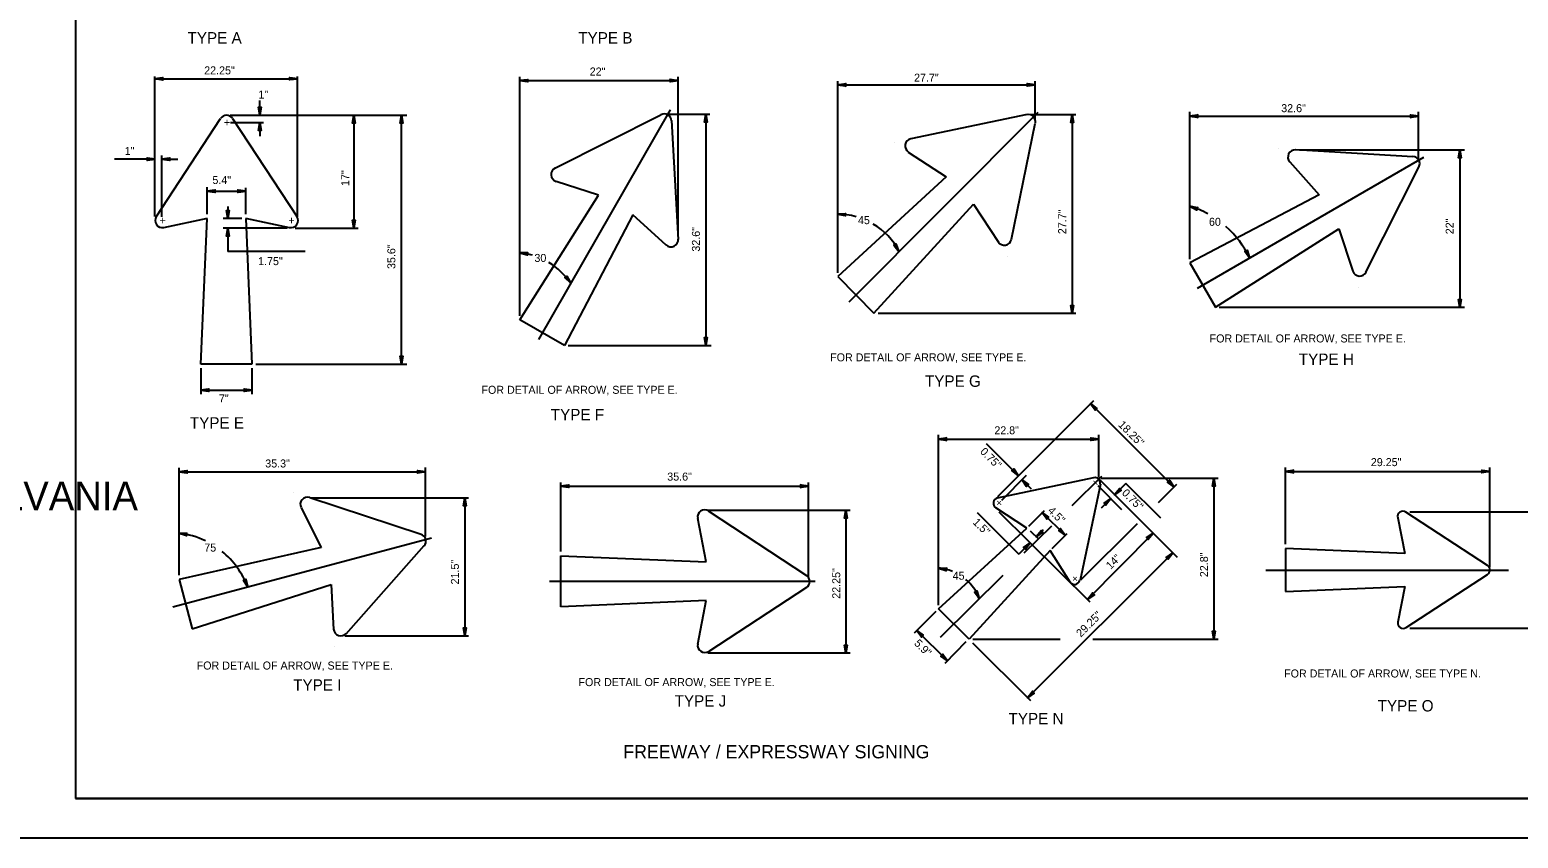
# Model space of a CAD drawing. Extents: x 638421 to 641849, y 297270 to 299646.
# Drawn here: x 640967 to 641529, y 298458 to 298763 of the extents above; entities that cross this region are included whole.
import ezdxf

# ---------------------------------------------------------------- set-up
doc = ezdxf.new("R2010")
doc.units = 0
for name, color, linetype in [('1', 7, 'Continuous'), ('2', 7, 'Continuous'), ('3', 7, 'Continuous'), ('XCS-GRID-HVGL', 7, 'Continuous')]:
    doc.layers.add(name, color=color, linetype=linetype)

# ---------------------------------------------------------------- blocks, each defined once
blk = doc.blocks.new('RARROW')
at = {"layer": '3'}
blk.add_lwpolyline([(-2.2695, 0.285), (-2.184875, 0.12075), (0, 0), (-2.2695, 0.285), (-2.38575, 0.384625), (0, 0), (-2.183125, -0.108), (-2.262875, -0.2705), (0, 0), (-2.38575, -0.379125), (-2.262875, -0.2705)], dxfattribs=at)

msp = doc.modelspace()

# ---------------------------------------------------------------- linework, layer by layer
at = {"layer": '1'}
for p, q in [((640984.31, 299036.63), (640984.31, 298472.63)), ((641770.31, 298472.63), (640984.31, 298472.63)), ((640984.31, 298472.63), (641570.31, 298472.63))]:
    msp.add_line(p, q, dxfattribs=at)
at = {"layer": '2'}
for p, q in [((641014.31, 298692.13), (641014.31, 298745)), ((641014.31, 298744.13), (641068.06, 298744.13)), ((641068.06, 298692), (641068.06, 298745)), ((641152.06, 298654.63), (641152.06, 298744.88)), ((641152.06, 298743.38), (641211.81, 298743.38)), ((641211.81, 298685.13), (641211.81, 298744.88)), ((641272.06, 298670.88), (641272.06, 298743.25)), ((641272.06, 298741.75), (641346.56, 298741.75)), ((641346.56, 298729), (641346.56, 298743.25)), ((641053.94, 298730.38), (641053.94, 298735.88)), ((641042.69, 298730.38), (641109.36, 298730.38)), ((641042.69, 298730.38), (641091.06, 298730.38)), ((641044.19, 298730.38), (641055.31, 298730.38)), ((641089.44, 298730.38), (641089.44, 298687.75)), ((641107.36, 298636.5), (641107.36, 298730.38)), ((641159.19, 298645.75), (641208.94, 298732.38)), ((641165.31, 298710.38), (641205.31, 298730.5)), ((641208.06, 298730.75), (641223.81, 298730.75)), ((641208.94, 298732.38), (641208.94, 298732.38)), ((641208.94, 298732.38), (641208.94, 298732.38)), ((641222.31, 298730.75), (641222.31, 298643.5)), ((641276.31, 298660), (641347.69, 298731.5)), ((641343.56, 298730.63), (641299.69, 298721.38)), ((641344.94, 298730.63), (641361.94, 298730.63)), ((641347.56, 298731.38), (641347.56, 298731.38)), ((641347.56, 298731.38), (641347.56, 298731.38)), ((641360.56, 298730.63), (641360.56, 298655.63)), ((641404.94, 298676), (641404.94, 298731.63)), ((641404.94, 298730), (641491.31, 298730)), ((641491.31, 298713.63), (641491.31, 298731.63)), ((641014.81, 298692), (641039.06, 298729.13)), ((641042.81, 298727.63), (641055.31, 298727.63)), ((641043.56, 298729.13), (641067.94, 298692)), ((641053.94, 298727.63), (641053.94, 298722.5)), ((641209.31, 298728.38), (641211.81, 298683.5)), ((641337.69, 298683.63), (641346.56, 298727.25)), ((641293.31, 298720.13), (641293.31, 298720.13)), ((641014.31, 298713.75), (640999.05, 298713.75)), ((641014.31, 298692.13), (641014.31, 298715.13)), ((641016.94, 298692), (641016.94, 298715.13)), ((641016.94, 298713.75), (641022.94, 298713.75)), ((641298.69, 298716.38), (641312.94, 298707.13)), ((641407.81, 298665.13), (641493.31, 298714.5)), ((641438.31, 298717.63), (641438.31, 298717.63)), ((641442.69, 298712.75), (641453.81, 298700.25)), ((641489.19, 298714.63), (641444.94, 298717.25)), ((641446.31, 298717.25), (641508.69, 298717.25)), ((641493.31, 298714.5), (641493.31, 298714.5)), ((641493.31, 298714.5), (641493.31, 298714.5)), ((641506.94, 298717.25), (641506.94, 298657.88)), ((641312.94, 298707.13), (641272.06, 298669.5)), ((641312.94, 298707.13), (641312.94, 298707.13)), ((641471.44, 298671.13), (641491.44, 298710.75)), ((641034.06, 298693), (641034.06, 298703.16)), ((641034.06, 298701.71), (641048.56, 298701.71)), ((641048.56, 298693), (641048.56, 298702.92)), ((641181.81, 298700.13), (641165.81, 298705.38)), ((641318.19, 298702), (641318.19, 298702)), ((641041.81, 298695.88), (641041.81, 298691.38)), ((641152.06, 298653.13), (641181.81, 298700.13)), ((641181.81, 298700.13), (641181.81, 298700.13)), ((641188.31, 298696.38), (641188.31, 298696.38)), ((641285.69, 298655.63), (641323.31, 298696.75)), ((641323.31, 298696.75), (641323.31, 298696.75)), ((641323.31, 298696.75), (641332.69, 298682.5)), ((641453.81, 298700.25), (641404.94, 298674.63)), ((641453.81, 298700.25), (641453.81, 298700.25)), ((641034.06, 298691.38), (641017.56, 298687.88)), ((641031.69, 298636.5), (641034.06, 298691.38)), ((641034.06, 298691.38), (641034.06, 298691.38)), ((641047.06, 298691.38), (641040.06, 298691.38)), ((641041.44, 298691.38), (641041.44, 298691.38)), ((641048.56, 298691.38), (641048.56, 298691.38)), ((641065.06, 298687.88), (641048.56, 298691.38)), ((641048.56, 298691.38), (641050.94, 298636.5)), ((641194.69, 298692.75), (641168.94, 298643.5)), ((641194.69, 298692.75), (641194.69, 298692.75)), ((641207.31, 298681.38), (641194.69, 298692.75)), ((641457.44, 298693.88), (641457.44, 298693.88)), ((641064.19, 298687.75), (641040.06, 298687.75)), ((641041.81, 298687.75), (641041.81, 298678.88)), ((641067.19, 298687.75), (641091.06, 298687.75)), ((641414.69, 298657.88), (641461.19, 298687.5)), ((641461.19, 298687.5), (641461.19, 298687.5)), ((641461.19, 298687.5), (641466.44, 298671.5)), ((641071.07, 298678.88), (641041.81, 298678.88)), ((641336.31, 298677), (641336.31, 298677)), ((641404.94, 298674.63), (641404.94, 298674.63)), ((641404.94, 298674.63), (641414.69, 298657.88)), ((641272.06, 298669.5), (641272.06, 298669.5)), ((641272.06, 298669.5), (641285.69, 298655.63)), ((641468.56, 298665.25), (641468.56, 298665.25)), ((641414.69, 298657.88), (641414.69, 298657.88)), ((641416.06, 298657.88), (641508.69, 298657.88)), ((641152.06, 298653.13), (641152.06, 298653.13)), ((641168.94, 298643.5), (641152.06, 298653.13)), ((641285.69, 298655.63), (641285.69, 298655.63)), ((641287.31, 298655.63), (641361.94, 298655.63)), ((641168.94, 298643.5), (641168.94, 298643.5)), ((641170.31, 298643.5), (641224.31, 298643.5)), ((641050.94, 298636.5), (641031.69, 298636.5)), ((641031.69, 298634.88), (641031.69, 298625.13)), ((641050.94, 298634.88), (641050.94, 298625.13)), ((641052.44, 298636.5), (641109.36, 298636.5)), ((641031.69, 298626.63), (641050.94, 298626.63)), ((641332.44, 298586.5), (641368.69, 298622.75)), ((641398.94, 298590.13), (641367.5, 298621.56)), ((641310.06, 298545.5), (641310.06, 298609.75)), ((641310.06, 298608.13), (641370.56, 298608.13)), ((641340.16, 298594.46), (641328.18, 298606.45)), ((641370.56, 298593.75), (641370.56, 298609.75)), ((641023.44, 298556.88), (641023.44, 298597.38)), ((641023.44, 298595.88), (641116.44, 298595.88)), ((641116.44, 298571.38), (641116.44, 298597.5)), ((641333.94, 298585.13), (641343.31, 298594.63)), ((641441.06, 298568.5), (641441.06, 298597.5)), ((641441.06, 298596), (641518.19, 298596)), ((641518.19, 298560), (641518.19, 298597.5)), ((641167.56, 298565.75), (641167.56, 298591.75)), ((641167.56, 298590.38), (641261.06, 298590.38)), ((641261.06, 298556.13), (641261.06, 298591.75)), ((641332.31, 298586), (641368.69, 298593.63)), ((641345.16, 298589.35), (641341.66, 298592.85)), ((641360.56, 298583.13), (641371.69, 298594.13)), ((641371.19, 298591.13), (641363.56, 298555)), ((641370.19, 298590.63), (641379.19, 298581.63)), ((641370.56, 298593.13), (641400.16, 298563.7)), ((641371.44, 298593.38), (641415.69, 298593.38)), ((641371.69, 298594.13), (641371.69, 298594.13)), ((641371.69, 298594.13), (641371.69, 298594.13)), ((641380.83, 298591.46), (641376.55, 298587.17)), ((641394, 298578.29), (641380.83, 298591.46)), ((641393.12, 298584.23), (641400.06, 298591.13)), ((641414.06, 298593.38), (641414.06, 298532.75)), ((641066.56, 298588.13), (641066.56, 298588.13)), ((641114.81, 298572.25), (641072.81, 298586)), ((641073.19, 298586), (641132.69, 298586)), ((641131.31, 298586), (641131.31, 298534)), ((641375.1, 298585.71), (641371.55, 298582.15)), ((641069.56, 298582.25), (641077.06, 298567.25)), ((641222.44, 298561.88), (641219.19, 298578.25)), ((641223.06, 298581.38), (641276.69, 298581.38)), ((641223.19, 298581.13), (641260.28, 298556.69)), ((641275.06, 298581.38), (641275.06, 298527.5)), ((641324.74, 298580.45), (641340.44, 298564.75)), ((641343.44, 298574.63), (641331.69, 298582.25)), ((641332.93, 298580.71), (641367.2, 298546.75)), ((641344.19, 298575.38), (641350.08, 298581.27)), ((641349.26, 298580.51), (641357.89, 298571.88)), ((641483.43, 298578.51), (641486.19, 298565)), ((641517.36, 298560.51), (641486.53, 298580.61)), ((641488.06, 298580.75), (641541.69, 298580.75)), ((641310.06, 298544.13), (641343.44, 298574.63)), ((641342.44, 298565.25), (641352.88, 298575.47)), ((641343.44, 298574.63), (641343.44, 298574.63)), ((641344.69, 298573.63), (641347.94, 298570.38)), ((641347, 298571.32), (641349.69, 298574.13)), ((641352.94, 298566.88), (641358.65, 298572.58)), ((641363.81, 298555.13), (641385.16, 298576.33)), ((641366.44, 298547.75), (641391.12, 298572.69)), ((641021.06, 298544.88), (641118.69, 298570.88)), ((641077.06, 298567.25), (641023.44, 298555.25)), ((641077.06, 298567.25), (641077.06, 298567.25)), ((641086.44, 298534.75), (641115.94, 298568)), ((641118.69, 298570.88), (641118.69, 298570.88)), ((641118.69, 298570.88), (641118.69, 298570.88)), ((641344.72, 298569.03), (641340.44, 298564.75)), ((641486.19, 298565), (641441.06, 298566.88)), ((641441.06, 298566.88), (641441.06, 298550.63)), ((641167.56, 298564.13), (641222.44, 298561.88)), ((641167.56, 298544.88), (641167.56, 298564.13)), ((641352.19, 298566.13), (641321.69, 298532.75)), ((641398.59, 298565.26), (641343.69, 298510.63)), ((641352.19, 298566.13), (641352.19, 298566.13)), ((641359.81, 298554.25), (641352.19, 298566.13)), ((641023.44, 298555.25), (641023.44, 298555.25)), ((641023.44, 298555.25), (641028.31, 298536.63)), ((641078.94, 298560.38), (641078.94, 298560.38)), ((641310.84, 298533.43), (641334.45, 298556.91)), ((641433.64, 298558.75), (641525.22, 298558.75)), ((641486.58, 298537.05), (641517.36, 298557.12)), ((641520.06, 298558.75), (641520.06, 298558.75)), ((641520.06, 298558.75), (641520.06, 298558.75)), ((641028.31, 298536.63), (641080.81, 298553.38)), ((641080.81, 298553.38), (641080.81, 298553.38)), ((641080.81, 298553.38), (641081.69, 298536.38)), ((641163.19, 298554.63), (641263.56, 298554.63)), ((641222.44, 298554.63), (641222.44, 298554.63)), ((641260.26, 298552.18), (641223.34, 298528.1)), ((641263.56, 298554.63), (641263.56, 298554.63)), ((641263.56, 298554.63), (641263.56, 298554.63)), ((641441.06, 298550.63), (641486.19, 298552.63)), ((641486.19, 298552.63), (641483.49, 298539.15)), ((641222.44, 298547.25), (641167.56, 298544.88)), ((641219.21, 298530.88), (641222.44, 298547.25)), ((641321.69, 298532.75), (641310.06, 298544.13)), ((641309.06, 298543.13), (641300.94, 298535)), ((641028.31, 298536.63), (641028.31, 298536.63)), ((641085.94, 298534), (641132.69, 298534)), ((641301.94, 298536), (641313.44, 298524.5)), ((641323.06, 298532.75), (641356.05, 298532.75)), ((641368.32, 298532.75), (641415.69, 298532.75)), ((641488.06, 298536.88), (641541.69, 298536.88)), ((641082.06, 298530), (641082.06, 298530)), ((641223.06, 298527.5), (641276.69, 298527.5)), ((641320.44, 298531.75), (641312.44, 298523.5)), ((641344.94, 298509.5), (641323.06, 298531.25))]:
    msp.add_line(p, q, dxfattribs=at)
for centre, radius, start, end in [((641041.34, 298727.63), 2.7, 33.2602, 146.7398), ((641206.56, 298728.11), 2.73, 3.2602, 116.7398), ((641344.03, 298727.85), 2.73, 348.2602, 101.7398), ((641300.22, 298718.74), 2.73, 101.7398, 236.6838), ((641444.71, 298714.56), 2.71, 86.7398, 221.6838), ((641489.03, 298712.03), 2.71, 333.2602, 86.7398), ((641166.6, 298707.98), 2.73, 116.7398, 251.6838), ((641394.38, 298660.95), 36.6, 61.5747, 73.2376), ((641017.07, 298690.62), 2.7, 146.7398, 281.6838), ((641065.62, 298690.62), 2.7, 258.3162, 33.2602), ((641272.16, 298667.06), 25.91, 74.7149, 90.4248), ((641272.16, 298667.06), 25.91, 27.3961, 59.0898), ((641394.38, 298660.95), 36.6, 25.1573, 48.5866), ((641209.11, 298683.44), 2.73, 228.3162, 3.2602), ((641334.92, 298684.04), 2.73, 213.3162, 348.2602), ((641149.13, 298651.72), 26.9, 73.3784, 83.7749), ((641149.13, 298651.72), 26.9, 34.588, 58.9608), ((641469.06, 298672.38), 2.71, 198.3162, 333.2602), ((641369.09, 298591.64), 2.02, 348.0958, 101.9043), ((641369.09, 298591.64), 2.02, 348.0958, 101.9043), ((641071.87, 298583.54), 2.7, 71.7398, 206.6838), ((641332.81, 298583.99), 2.02, 101.9042, 237.308), ((641332.81, 298583.99), 2.02, 101.9042, 237.308), ((641221.83, 298578.8), 2.7, 56.7398, 191.6838), ((641485.42, 298578.92), 2.03, 56.8956, 191.5138), ((641019.68, 298541.22), 31.67, 64.3786, 83.3665), ((641113.9, 298569.68), 2.7, 318.2602, 71.7398), ((641019.68, 298541.22), 31.67, 20.6208, 50.9228), ((641258.79, 298554.44), 2.7, 303.1054, 56.6238), ((641308.66, 298541.48), 18.08, 68.18, 85.2977), ((641308.66, 298541.48), 18.08, 21.3254, 49.4675), ((641516.25, 298558.81), 2.02, 303.1044, 56.8956), ((641361.44, 298555.37), 2.02, 212.692, 348.0958), ((641361.44, 298555.37), 2.02, 212.692, 348.0958), ((641485.48, 298538.75), 2.02, 168.6901, 303.1044), ((641084.44, 298536.65), 2.7, 183.3162, 318.2602), ((641221.86, 298530.36), 2.7, 168.8571, 303.1054)]:
    msp.add_arc(centre, radius, start, end, dxfattribs=at)
at = {"layer": 'XCS-GRID-HVGL'}
msp.add_lwpolyline([(640944.31, 299051.63), (641785.31, 299051.63), (641785.31, 298457.63), (640944.31, 298457.63)], close=True, dxfattribs=at)

# ---------------------------------------------------------------- block references
at = {"layer": '2'}
for p, xscale, yscale, rotation in [((641014.31, 298744.13), 1.2574347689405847, 1.3092961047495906, 180), ((641152.06, 298743.38), 1.2574347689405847, 1.3092961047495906, 180), ((641272.06, 298741.75), 1.2574347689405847, 1.3092961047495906, 180), ((641053.94, 298730.38), 1.2574347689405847, 1.3092961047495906, -90.00000000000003), ((641089.44, 298730.38), 1.2574347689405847, 1.3092961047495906, 89.99999999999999), ((641107.36, 298730.38), 1.2574347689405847, 1.3092961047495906, 89.99999999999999), ((641222.31, 298730.75), 1.2574347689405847, 1.3092961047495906, 89.99999999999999), ((641360.56, 298730.63), 1.2574347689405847, 1.3092961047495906, 89.99999999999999), ((641404.94, 298730), 1.2574347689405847, 1.3092961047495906, 180), ((641053.94, 298727.63), 1.2574347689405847, 1.3092961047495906, 89.99999999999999), ((641016.94, 298713.75), 1.2574347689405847, 1.3092961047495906, 180), ((641506.94, 298717.25), 1.2574347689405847, 1.3092961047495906, 89.99999999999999), ((641034.06, 298701.71), 1.2574347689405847, 1.3092961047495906, 180), ((641404.94, 298695.99), 1.2574347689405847, 1.3092961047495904, 160.9599901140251), ((641041.81, 298691.38), 1.2574347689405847, 1.3092961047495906, -90.00000000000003), ((641089.44, 298687.75), 1.2574347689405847, 1.3092961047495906, -90.00000000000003), ((641271.97, 298692.97), 1.2574347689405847, 1.3092961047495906, 177.36930512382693), ((641041.81, 298687.75), 1.2574347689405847, 1.3092961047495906, 89.99999999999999), ((641152.05, 298678.47), 1.2574347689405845, 1.3092961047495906, 171.05823265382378), ((641295.16, 298678.98), 1.2574347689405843, 1.3092961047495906, -58.541379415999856), ((641427.51, 298676.51), 1.257434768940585, 1.309296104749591, -62.66084078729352), ((641171.28, 298667), 1.2574347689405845, 1.3092961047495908, -52.4271792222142), ((641360.56, 298655.63), 1.2574347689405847, 1.3092961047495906, -90.00000000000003), ((641506.94, 298657.88), 1.2574347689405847, 1.3092961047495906, -90.00000000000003), ((641222.31, 298643.5), 1.2574347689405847, 1.3092961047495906, -90.00000000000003), ((641107.36, 298636.5), 1.2574347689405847, 1.3092961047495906, -90.00000000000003), ((641031.69, 298626.63), 1.2574347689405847, 1.3092961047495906, 180), ((641367.5, 298621.56), 1.257434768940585, 1.3092961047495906, 133.27939444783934), ((641310.06, 298608.13), 1.2574347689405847, 1.3092961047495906, 180), ((641023.44, 298595.88), 1.2574347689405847, 1.3092961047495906, 180), ((641340.16, 298594.46), 1.257434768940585, 1.3092961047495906, -46.72060555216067), ((641441.06, 298596), 1.2574347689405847, 1.3092961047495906, 180), ((641167.56, 298590.38), 1.2574347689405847, 1.3092961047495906, 180), ((641341.66, 298592.85), 1.257434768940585, 1.3092961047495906, 133.27939444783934), ((641376.55, 298587.17), 1.2574347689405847, 1.3092961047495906, -136.72060555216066), ((641398.94, 298590.13), 1.257434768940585, 1.3092961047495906, -46.72060555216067), ((641414.06, 298593.38), 1.2574347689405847, 1.3092961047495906, 89.99999999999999), ((641131.31, 298586), 1.2574347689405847, 1.3092961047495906, 89.99999999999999), ((641375.1, 298585.71), 1.257434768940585, 1.3092961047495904, 43.27939444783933), ((641275.06, 298581.38), 1.2574347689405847, 1.3092961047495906, 89.99999999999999), ((641349.26, 298580.51), 1.257434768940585, 1.3092961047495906, 133.27939444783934), ((641023.34, 298572.68), 1.2574347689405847, 1.3092961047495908, 171.6158607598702), ((641347, 298571.32), 1.2574347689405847, 1.3092961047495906, -136.72060555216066), ((641357.89, 298571.88), 1.257434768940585, 1.3092961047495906, -46.72060555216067), ((641391.12, 298572.69), 1.257434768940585, 1.3092961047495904, 43.27939444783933), ((641344.72, 298569.03), 1.257434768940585, 1.3092961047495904, 43.27939444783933), ((641398.59, 298565.26), 1.257434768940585, 1.3092961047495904, 43.27939444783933), ((641049.32, 298552.37), 1.2574347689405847, 1.309296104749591, -67.61237387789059), ((641310.15, 298559.49), 1.2574347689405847, 1.3092961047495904, 170.0803574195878), ((641325.5, 298548.05), 1.2574347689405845, 1.3092961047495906, -62.77863824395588), ((641366.44, 298547.75), 1.2574347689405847, 1.3092961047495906, -136.72060555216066), ((641131.31, 298534), 1.2574347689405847, 1.3092961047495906, -90.00000000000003), ((641301.94, 298536), 1.257434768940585, 1.3092961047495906, 133.27939444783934), ((641414.06, 298532.75), 1.2574347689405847, 1.3092961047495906, -90.00000000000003), ((641275.06, 298527.5), 1.2574347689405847, 1.3092961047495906, -90.00000000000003), ((641313.44, 298524.5), 1.257434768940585, 1.3092961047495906, -46.72060555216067), ((641343.69, 298510.63), 1.2574347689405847, 1.3092961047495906, -136.72060555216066)]:
    msp.add_blockref('RARROW', p, dxfattribs=dict(at, xscale=xscale, yscale=yscale, rotation=rotation))
at = {"layer": '2', "xscale": 1.2574347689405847, "yscale": 1.3092961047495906}
for p in [(641068.06, 298744.13), (641211.81, 298743.38), (641346.56, 298741.75), (641491.31, 298730), (641014.31, 298713.75), (641048.56, 298701.71), (641050.94, 298626.63), (641370.56, 298608.13), (641116.44, 298595.88), (641518.19, 298596), (641261.06, 298590.38)]:
    msp.add_blockref('RARROW', p, dxfattribs=at)

# ---------------------------------------------------------------- texts
at = {"layer": '1'}
msp.add_text('COMMONWEALTH OF PENNSYLVANIA', height=10.7828, dxfattribs=at).set_placement((640741.9, 298581.36))
at = {"layer": '2'}
for s, height, p in [('TYPE A', 4.3, (641026.61, 298757.39)), ('TYPE B', 4.3, (641174.11, 298757.39)), ('22.25"', 3.022, (641032.9, 298745.74)), ('22"', 3.022, (641178.43, 298745.32)), ('27.7"', 3.022, (641300.86, 298742.99)), ('1"', 3.022, (641053.38, 298736.64)), ('32.6"', 3.022, (641439.47, 298731.49)), ('+', 3.02, (641040.31, 298726.13)), ('1"', 3.022, (641002.89, 298715.35)), ('5.4"', 3.022, (641036, 298704.39)), ('+', 3.02, (641016.06, 298689.13)), ('+', 3.02, (641064.69, 298689.13)), ('45', 3.022, (641279.69, 298689.25)), ('60', 3.022, (641412.19, 298688.63)), ('1.75"', 3.022, (641053.26, 298673.8)), ('30', 3.022, (641157.56, 298675)), ('FOR DETAIL OF ARROW, SEE TYPE E.', 3.0217, (641412.44, 298644.63)), ('FOR DETAIL OF ARROW, SEE TYPE E.', 3.0217, (641269.19, 298637.5)), ('TYPE H', 4.3, (641446.11, 298636.14)), ('FOR DETAIL OF ARROW, SEE TYPE E.', 3.0217, (641137.56, 298625.25)), ('TYPE G', 4.3, (641304.99, 298627.89)), ('7"', 3.022, (641038.46, 298621.99)), ('TYPE F', 4.3, (641163.74, 298615.26)), ('TYPE E', 4.3, (641027.49, 298612.14)), ('22.8"', 3, (641331.2, 298610)), ('35.3"', 3.022, (641055.94, 298597.47)), ('29.25"', 3.022, (641473.3, 298597.98)), ('35.6"', 3.022, (641207.7, 298592.51)), ('75', 3.022, (641032.94, 298565.75)), ('45', 3.022, (641315.44, 298555.13)), ('FOR DETAIL OF ARROW, SEE TYPE E.', 3.0217, (641030.06, 298521.25)), ('TYPE I', 4.3, (641066.49, 298513.26)), ('FOR DETAIL OF ARROW, SEE TYPE E.', 3.0217, (641174.19, 298515)), ('FOR DETAIL OF ARROW, SEE TYPE N.', 3.0217, (641440.56, 298518.25)), ('TYPE J', 4.3, (641210.49, 298507.26)), ('TYPE N', 4.3, (641336.53, 298500.59)), ('TYPE O', 4.3, (641475.88, 298505.43)), ('FREEWAY / EXPRESSWAY SIGNING', 5, (641191.12, 298487.75))]:
    msp.add_text(s, height=height, dxfattribs=at).set_placement(p)
for s, height, rotation, p in [('17"', 3.022, 90, (641087.65, 298703.65)), ('27.7"', 3.022, 90, (641358.29, 298685.48)), ('22"', 3.022, 90, (641504.56, 298685.44)), ('32.6"', 3.022, 90, (641220.04, 298678.87)), ('35.6"', 3.022, 90, (641105.06, 298672.33)), ('18.25"', 3.022, 315, (641377.75, 298613.33)), ('0.75"', 3, 315, (641325.56, 298603.2)), ('+', 3.02, 45, (641369.56, 298589.85)), ('0.75"', 3, 315, (641379.09, 298587.61)), ('+', 3.02, 45, (641333.19, 298582.25)), ('1.5"', 3, 315, (641322.84, 298576.55)), ('4.5"', 3, 315, (641351.12, 298580.93)), ('21.5"', 3.022, 90, (641129.06, 298553.35)), ('14"', 3, 45, (641375.06, 298558.78)), ('22.8"', 3.022, 90, (641411.83, 298556.1)), ('22.25"', 3.022, 90, (641273.01, 298547.95)), ('+', 3.02, 45, (641361.81, 298553.63)), ('29.25"', 3.022, 45, (641363.85, 298533.25)), ('5.9"', 3, 315, (641300.68, 298530.89))]:
    msp.add_text(s, height=height, rotation=rotation, dxfattribs=at).set_placement(p)

doc.saveas('drawing.dxf')
